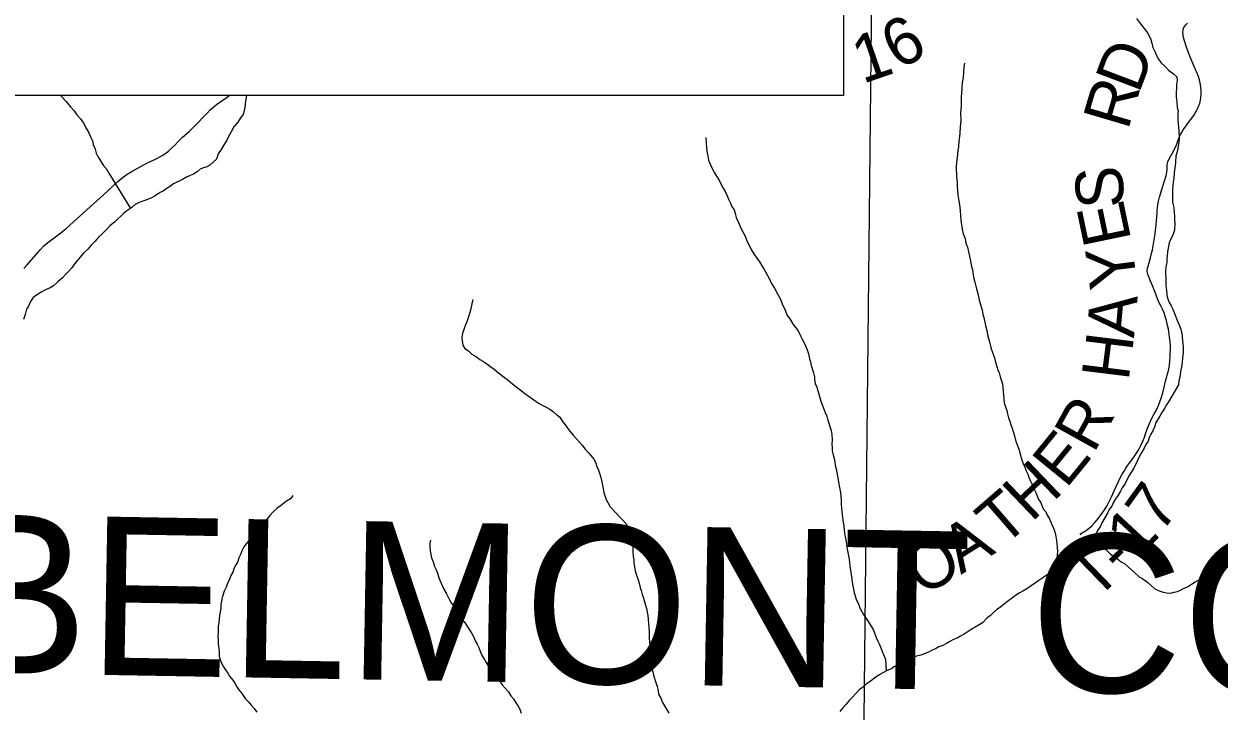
# Model space of a CAD drawing. Extents: x 0 to 34, y 0 to 22.
# Drawn here: x 27.832 to 29.261, y 14.653 to 15.474 of the extents above; entities that cross this region are included whole.
import ezdxf

# ---------------------------------------------------------------- set-up
doc = ezdxf.new("R2010")
doc.units = 0
for name, color, linetype in [('GM_X_Corporation', 7, 'Continuous'), ('GM_X_County_Text', 7, 'Continuous'), ('GM_X_Minor_River', 7, 'Continuous'), ('GM_X_Township_Road', 7, 'Continuous'), ('GM_X_Township_Road_Text', 7, 'Continuous'), ('SH_Data', 7, 'Continuous')]:
    doc.layers.add(name, color=color, linetype=linetype)

msp = doc.modelspace()

# ---------------------------------------------------------------- linework, layer by layer
at = {"layer": 'GM_X_Corporation'}
msp.add_lwpolyline([(28.8464, 15.5116), (29.8543, 15.4933), (29.8316, 14.4749), (28.8354, 14.4926)], close=True, dxfattribs=at)
at = {"layer": 'GM_X_Minor_River'}
for points in [[(29.1627, 15.4808), (29.1673, 15.4744), (29.172, 15.4688), (29.1758, 15.4636), (29.1782, 15.4594), (29.1798, 15.4557), (29.181, 15.4515), (29.1822, 15.4462), (29.1849, 15.4406), (29.1865, 15.4365), (29.1889, 15.4323), (29.1916, 15.4282), (29.1974, 15.423), (29.2008, 15.4193), (29.207, 15.4148), (29.2108, 15.4111), (29.2113, 15.4066), (29.2106, 15.402), (29.2103, 15.3978), (29.21, 15.3925), (29.2101, 15.3872), (29.211, 15.3808), (29.2114, 15.3744), (29.2123, 15.3706), (29.212, 15.3668), (29.2121, 15.3592), (29.213, 15.3505), (29.2134, 15.3467), (29.2136, 15.338), (29.2133, 15.3327), (29.2126, 15.3281), (29.2116, 15.3232), (29.2098, 15.3163), (29.2092, 15.3091), (29.2089, 15.3042), (29.2082, 15.3), (29.2075, 15.2954), (29.2072, 15.2905), (29.2066, 15.2852), (29.2059, 15.2772), (29.2057, 15.2715), (29.2058, 15.2613), (29.2071, 15.2549), (29.2076, 15.2484), (29.208, 15.2446), (29.2081, 15.2401), (29.2086, 15.2356), (29.2079, 15.2276), (29.2061, 15.2219), (29.2025, 15.215), (29.2014, 15.2104), (29.1997, 15.202), (29.1994, 15.1971), (29.1991, 15.1933), (29.1988, 15.1888), (29.1977, 15.1838), (29.1974, 15.1789), (29.1977, 15.1664), (29.1977, 15.1611), (29.1986, 15.1562), (29.1991, 15.1497), (29.2003, 15.1456), (29.2019, 15.1411), (29.2042, 15.1373), (29.2062, 15.1332), (29.2085, 15.1271), (29.2109, 15.1207), (29.2133, 15.1155), (29.2157, 15.1095), (29.2165, 15.1057), (29.2173, 15.1015), (29.2178, 15.0947), (29.2183, 15.089), (29.2184, 15.0849), (29.2184, 15.0811), (29.2178, 15.075), (29.2171, 15.0693), (29.2165, 15.064), (29.2154, 15.0587), (29.2144, 15.0518), (29.2133, 15.0476), (29.2127, 15.0427)], [(28.957, 15.4274), (28.9563, 15.4236), (28.9557, 15.4164), (28.9554, 15.4103), (28.9544, 15.4043), (28.9535, 15.3917), (28.9532, 15.3872), (28.9529, 15.3807), (28.953, 15.3762), (28.9524, 15.3675), (28.9525, 15.3591), (28.9519, 15.3512), (28.9513, 15.3439), (28.951, 15.3394), (28.9503, 15.3344), (28.9497, 15.3272), (28.949, 15.3234), (28.9484, 15.3143), (28.9473, 15.309), (28.9471, 15.3029), (28.9473, 15.2919), (28.9481, 15.2851), (28.9482, 15.2791), (28.9487, 15.2753), (28.9491, 15.27), (28.9504, 15.2628), (28.9513, 15.2552), (28.9518, 15.2507), (28.9527, 15.2397), (28.9544, 15.2291), (28.9556, 15.2235), (28.9576, 15.2178), (28.9585, 15.2121), (28.9604, 15.2076), (28.9617, 15.202), (28.9629, 15.1967), (28.9641, 15.191), (28.965, 15.1857), (28.9666, 15.1801), (28.9679, 15.1714), (28.9695, 15.1657), (28.9715, 15.1574), (28.9732, 15.1502), (28.9744, 15.1442), (28.976, 15.1389), (28.978, 15.1321), (28.9789, 15.1268), (28.9801, 15.1231), (28.9821, 15.1136), (28.9837, 15.1076), (28.9846, 15.1027), (28.9858, 15.0982), (28.987, 15.094), (28.989, 15.0857), (28.9914, 15.0793), (28.993, 15.0752), (28.9942, 15.0699), (28.9958, 15.0646), (28.9967, 15.0608), (28.9986, 15.0571), (28.9998, 15.0525), (29.0011, 15.0476), (29.0023, 15.0439)], [(27.8765, 15.3888), (27.8774, 15.3875), (27.8828, 15.3816), (27.8882, 15.3752), (27.8925, 15.3704), (27.8956, 15.3655), (27.9002, 15.361), (27.9037, 15.3558), (27.9072, 15.349), (27.9099, 15.3441), (27.9123, 15.3385), (27.9143, 15.3347), (27.9151, 15.3302), (27.9175, 15.3246), (27.9187, 15.32), (27.9206, 15.3159), (27.9238, 15.3106), (27.9273, 15.3054), (27.9307, 15.3013)], [(28.0983, 15.3888), (28.0977, 15.3846), (28.097, 15.3789), (28.0967, 15.3743), (28.0946, 15.366), (28.0913, 15.3621), (28.0883, 15.3568), (28.0835, 15.3514)], [(28.0835, 15.3514), (28.0802, 15.3452), (28.0769, 15.3399), (28.0751, 15.3353), (28.0721, 15.3311), (28.0681, 15.3242), (28.0648, 15.3192), (28.0626, 15.3127), (28.0548, 15.3054), (28.051, 15.3034), (28.0469, 15.3022), (28.0431, 15.3006), (28.0394, 15.2975), (28.0353, 15.2948), (28.0311, 15.2932), (28.0266, 15.2912), (28.0218, 15.2885), (28.0113, 15.283), (28.0075, 15.2803), (28.0038, 15.2779), (27.9989, 15.2744), (27.9952, 15.2729), (27.9892, 15.269), (27.9851, 15.2666), (27.9783, 15.2635), (27.9734, 15.2619), (27.9693, 15.2603), (27.9652, 15.2583), (27.9614, 15.2548), (27.9554, 15.2509), (27.9513, 15.2478), (27.9405, 15.2374), (27.9349, 15.2328), (27.9312, 15.2285), (27.9257, 15.2231), (27.9216, 15.2193), (27.9175, 15.2146), (27.9126, 15.2096), (27.9089, 15.205), (27.9037, 15.2004), (27.893, 15.1873), (27.8897, 15.1827), (27.8859, 15.1788), (27.8822, 15.1746), (27.8785, 15.1707), (27.8729, 15.1661), (27.8677, 15.1611), (27.8636, 15.1587), (27.8583, 15.1564), (27.8538, 15.154), (27.8486, 15.1509), (27.8433, 15.1474), (27.8404, 15.1424), (27.8378, 15.137), (27.8356, 15.1332), (27.8339, 15.1267), (27.8317, 15.121)], [(28.6479, 15.3386), (28.648, 15.3321), (28.6485, 15.3268), (28.6489, 15.3223), (28.6502, 15.3162), (28.651, 15.3113), (28.6534, 15.3057), (28.6557, 15.3008), (28.6581, 15.2963), (28.6604, 15.2925), (28.6631, 15.2884), (28.6663, 15.2816), (28.6686, 15.2779), (28.671, 15.2738), (28.6733, 15.2689), (28.6749, 15.2647), (28.6773, 15.2599), (28.6788, 15.2561), (28.6816, 15.252), (28.6828, 15.2478), (28.684, 15.2429), (28.6867, 15.2369), (28.6899, 15.2294), (28.693, 15.2237), (28.6954, 15.2185), (28.6973, 15.2143), (28.6993, 15.2106), (28.7024, 15.2038), (28.7052, 15.1993), (28.7087, 15.1941), (28.7118, 15.19), (28.7141, 15.1858), (28.7168, 15.1821), (28.7239, 15.1693), (28.7262, 15.1641), (28.7297, 15.1584), (28.7336, 15.1517), (28.7368, 15.1453), (28.7395, 15.1385), (28.7423, 15.1333), (28.745, 15.1257), (28.7481, 15.1216), (28.752, 15.1149), (28.7555, 15.1111), (28.7582, 15.1074), (28.761, 15.1014), (28.7629, 15.0972), (28.7653, 15.0931), (28.7669, 15.0893), (28.7688, 15.0848), (28.7704, 15.0799), (28.7717, 15.0739), (28.7729, 15.0701), (28.7737, 15.066), (28.7765, 15.0573), (28.7777, 15.0524), (28.7778, 15.0486), (28.7786, 15.0444), (28.7806, 15.0399)], [(27.9307, 15.3013), (27.9339, 15.296), (27.9596, 15.2536)], [(28.369, 15.1449), (28.3679, 15.1395), (28.3669, 15.1335), (28.3655, 15.1293), (28.3644, 15.1251), (28.3619, 15.1182), (28.3604, 15.1144), (28.3582, 15.109), (28.3568, 15.1045), (28.3561, 15.0995), (28.3562, 15.0954), (28.3571, 15.0901), (28.3594, 15.0863), (28.364, 15.0834), (28.3678, 15.0796), (28.3736, 15.0763), (28.3774, 15.073), (28.3812, 15.0712), (28.3858, 15.0678), (28.3908, 15.0641), (28.3946, 15.0615), (28.4, 15.0571), (28.4065, 15.0519), (28.4119, 15.0478), (28.4211, 15.0404), (28.4253, 15.0371), (28.4299, 15.0337)], [(28.7806, 15.0399), (28.7854, 15.0231), (28.7905, 15.0095), (28.7924, 15.0053), (28.7936, 15.0004), (28.7975, 14.9883), (28.7983, 14.9833), (28.7987, 14.9769), (28.7984, 14.9719), (28.7988, 14.9678), (28.7988, 14.964), (28.8, 14.959), (28.8012, 14.9545), (28.8019, 14.9507), (28.8024, 14.9465), (28.8035, 14.9424), (28.8043, 14.9378), (28.8051, 14.9336), (28.8059, 14.9291), (28.8067, 14.9241), (28.8087, 14.9139), (28.8091, 14.9097), (28.8095, 14.9044), (28.8096, 14.9002), (28.81, 14.8953), (28.8104, 14.8911), (28.8112, 14.8839), (28.812, 14.8786), (28.8128, 14.8737), (28.8132, 14.8695), (28.8136, 14.8657), (28.8144, 14.8611), (28.8152, 14.8573), (28.816, 14.8524), (28.8168, 14.846), (28.8184, 14.8384), (28.8192, 14.8342), (28.8196, 14.83), (28.8204, 14.8236), (28.8212, 14.8183), (28.8221, 14.8107), (28.8225, 14.8069), (28.8236, 14.8023), (28.8244, 14.7985), (28.8252, 14.794), (28.828, 14.7853), (28.8299, 14.7815), (28.8318, 14.7762), (28.8341, 14.7716), (28.8364, 14.7679), (28.8395, 14.7633), (28.8426, 14.7584), (28.848, 14.7494), (28.8499, 14.7448), (28.8514, 14.7407), (28.853, 14.7369), (28.8553, 14.7323), (28.8568, 14.7282), (28.8588, 14.7232), (28.8611, 14.7183), (28.8626, 14.7142), (28.8634, 14.7003)], [(29.2127, 15.0427), (29.2008, 15.0224), (29.1982, 15.0186), (29.196, 15.0144), (29.193, 15.0098), (29.1904, 15.0052), (29.1859, 14.9976), (29.1844, 14.9934), (29.1826, 14.9884), (29.1796, 14.9838), (29.1777, 14.9796), (29.1766, 14.9754), (29.174, 14.9712), (29.1718, 14.967), (29.1692, 14.9621), (29.1658, 14.9567), (29.1639, 14.9521), (29.1595, 14.943), (29.1565, 14.9388), (29.1539, 14.9342), (29.1516, 14.93), (29.149, 14.9246), (29.1457, 14.9197), (29.1434, 14.9155), (29.1408, 14.9109), (29.1374, 14.9063), (29.1348, 14.9017), (29.1333, 14.8975), (29.13, 14.8937), (29.1281, 14.8891), (29.1214, 14.8776), (29.1192, 14.8731), (29.1162, 14.8685), (29.1139, 14.8643), (29.1113, 14.8605), (29.1076, 14.8566), (29.1016, 14.849), (29.0971, 14.8447), (29.0933, 14.842), (29.0895, 14.839), (29.0854, 14.8351), (29.0756, 14.8278), (29.0711, 14.8251), (29.0673, 14.8224), (29.0632, 14.8201), (29.0591, 14.8174), (29.0545, 14.8147), (29.0508, 14.812), (29.0459, 14.8089), (29.0417, 14.8059), (29.0316, 14.7989), (29.0267, 14.7958), (29.0225, 14.7935), (29.018, 14.7908), (29.0142, 14.7881), (29.0101, 14.7847), (29.0048, 14.7808), (28.9999, 14.777), (28.9958, 14.7739), (28.9917, 14.7704), (28.9879, 14.767), (28.9838, 14.7635), (28.9785, 14.7582), (28.9744, 14.7555), (28.9699, 14.7528), (28.9661, 14.7508), (28.9612, 14.7477), (28.9567, 14.7447), (28.9521, 14.7423), (28.9484, 14.7396), (28.9439, 14.7381), (28.9393, 14.7358), (28.9356, 14.7334), (28.931, 14.7311), (28.9265, 14.7292), (28.9224, 14.7269), (28.9182, 14.7253), (28.9141, 14.723), (28.9046, 14.7195), (28.9008, 14.7187), (28.8967, 14.7171), (28.8914, 14.7148), (28.8873, 14.7132), (28.882, 14.7105), (28.8775, 14.7078), (28.8733, 14.7059), (28.8696, 14.7032), (28.8647, 14.7009), (28.8548, 14.6958), (28.8511, 14.6932), (28.8443, 14.6881), (28.8394, 14.6847), (28.8349, 14.6808), (28.8311, 14.6778), (28.8229, 14.6693), (28.8191, 14.6651), (28.8154, 14.6609), (28.8116, 14.6563), (28.8079, 14.6521)], [(29.0023, 15.0439), (29.0043, 15.0213), (29.0062, 15.0164), (29.0078, 15.0119), (29.0086, 15.0081), (29.0098, 15.0031), (29.0113, 14.9994), (29.0125, 14.9948), (29.014, 14.991), (29.0152, 14.9869), (29.0168, 14.9819), (29.0175, 14.9781), (29.0187, 14.9743), (29.0207, 14.969), (29.0222, 14.9645), (29.0238, 14.9588), (29.0253, 14.9543), (29.0273, 14.9482), (29.0292, 14.9444), (29.0307, 14.9399), (29.0327, 14.9361), (29.0338, 14.9323), (29.0358, 14.9274), (29.0385, 14.9229), (29.04, 14.9187), (29.0423, 14.9141), (29.0454, 14.9058), (29.0481, 14.902), (29.0493, 14.8983), (29.0512, 14.8945), (29.0543, 14.8907), (29.0558, 14.8869), (29.0581, 14.8831), (29.0604, 14.8786), (29.0643, 14.8695), (29.0655, 14.8653), (29.0663, 14.8612), (29.067, 14.8566), (29.0675, 14.8521), (29.0679, 14.8483), (29.0683, 14.8437), (29.068, 14.8392), (29.0657, 14.8215)], [(28.4299, 15.0337), (28.4477, 15.0208), (28.453, 15.0182), (28.4568, 15.016), (28.461, 15.0137), (28.4656, 15.0103), (28.4694, 15.0069), (28.4732, 15.0039), (28.4755, 15.0002), (28.4785, 14.9964), (28.4816, 14.9922), (28.4851, 14.9873), (28.4889, 14.9824), (28.4962, 14.9745), (28.5, 14.9707), (28.503, 14.9662), (28.508, 14.9609), (28.5141, 14.9534), (28.5161, 14.9489), (28.5172, 14.9451), (28.5195, 14.9405), (28.5211, 14.936), (28.5223, 14.9318), (28.5234, 14.9269), (28.5242, 14.9227), (28.525, 14.9189), (28.5258, 14.914), (28.527, 14.9102), (28.5285, 14.9057), (28.5305, 14.9019), (28.5335, 14.897), (28.5408, 14.889), (28.5439, 14.8853), (28.5481, 14.8811), (28.5519, 14.877), (28.5542, 14.8732), (28.5561, 14.869), (28.5577, 14.8653), (28.5592, 14.8603), (28.5604, 14.8558), (28.5605, 14.8474), (28.5605, 14.8429), (28.5609, 14.8376), (28.5617, 14.8338), (28.5618, 14.83), (28.5634, 14.8201), (28.5649, 14.8152), (28.5668, 14.8095), (28.568, 14.8057), (28.5692, 14.8004), (28.5704, 14.7966), (28.5715, 14.7921), (28.5731, 14.7875), (28.5754, 14.7792), (28.5766, 14.7754), (28.5774, 14.7708), (28.5782, 14.7667), (28.5786, 14.7625), (28.5794, 14.7526), (28.5799, 14.7469), (28.5799, 14.7393), (28.5808, 14.7317), (28.5808, 14.7237), (28.5812, 14.7192), (28.5817, 14.7124), (28.5825, 14.7078), (28.5833, 14.7032), (28.5844, 14.6995), (28.5852, 14.6953), (28.588, 14.6866), (28.5895, 14.682), (28.5907, 14.6771), (28.5911, 14.6729), (28.5938, 14.668), (28.5961, 14.6627), (28.5984, 14.6589), (28.6007, 14.6548), (28.6034, 14.6502)], [(28.154, 14.9102), (28.151, 14.9064), (28.1465, 14.9037), (28.1427, 14.901), (28.139, 14.898), (28.1352, 14.8953), (28.1307, 14.8914), (28.1262, 14.8864), (28.1232, 14.8826), (28.1198, 14.8788), (28.1161, 14.8742), (28.1119, 14.8696), (28.1089, 14.8654), (28.1048, 14.8612), (28.1018, 14.857), (28.0984, 14.8531), (28.0954, 14.8489), (28.0928, 14.8443), (28.0917, 14.8405), (28.0895, 14.836), (28.088, 14.8314), (28.0858, 14.8276), (28.0839, 14.8237), (28.0821, 14.8188), (28.0798, 14.8146), (28.078, 14.81), (28.0757, 14.8054), (28.0743, 14.8009), (28.0717, 14.7959), (28.0706, 14.7921), (28.0695, 14.7883), (28.0687, 14.7841), (28.068, 14.7803), (28.0677, 14.7757), (28.0669, 14.7712), (28.0662, 14.767), (28.0655, 14.7582), (28.0648, 14.754), (28.0645, 14.7502), (28.0645, 14.7457), (28.0642, 14.7419), (28.0646, 14.7373), (28.0646, 14.7324), (28.0654, 14.7274), (28.0658, 14.7229), (28.0659, 14.7183), (28.0671, 14.7138), (28.0686, 14.71), (28.0709, 14.7055), (28.0732, 14.7017), (28.0763, 14.6979), (28.0782, 14.6941), (28.082, 14.6896), (28.0847, 14.6858), (28.087, 14.6817), (28.0893, 14.6779), (28.0932, 14.673), (28.0966, 14.6681), (28.1008, 14.6636), (28.1042, 14.6598), (28.1077, 14.6556), (28.1108, 14.6511)], [(28.3184, 14.857), (28.3177, 14.8528), (28.3177, 14.8487), (28.3181, 14.8441), (28.3197, 14.8358), (28.3217, 14.8312), (28.3232, 14.8255), (28.3252, 14.8214), (28.3271, 14.8164), (28.3283, 14.8119), (28.3325, 14.8028), (28.3344, 14.7983), (28.3371, 14.7937), (28.341, 14.7862), (28.3433, 14.782), (28.3467, 14.7775), (28.3487, 14.7737), (28.3513, 14.7695), (28.3536, 14.7658), (28.3563, 14.762), (28.3598, 14.7578), (28.3678, 14.7454), (28.3705, 14.7408), (28.3721, 14.7367), (28.3744, 14.7325), (28.3763, 14.7284), (28.3782, 14.7231), (28.3802, 14.7185), (28.3829, 14.7144), (28.3852, 14.7106), (28.3879, 14.706), (28.3909, 14.7011), (28.3944, 14.6966), (28.3974, 14.6921), (28.402, 14.6875), (28.4043, 14.6838), (28.4078, 14.68), (28.4116, 14.6755), (28.4147, 14.6709), (28.4177, 14.6672), (28.4204, 14.6623), (28.4235, 14.6585), (28.4254, 14.6547), (28.427, 14.6502)], [(29.1113, 14.8604), (29.1316, 14.8401), (29.1358, 14.8375), (29.1403, 14.8341), (29.1445, 14.8311), (29.1487, 14.8285), (29.1605, 14.818), (29.1659, 14.8131), (29.1704, 14.8108), (29.1762, 14.8063), (29.18, 14.8026), (29.1845, 14.7988), (29.1899, 14.7962), (29.1944, 14.7947), (29.199, 14.794), (29.2035, 14.7937), (29.2077, 14.7949), (29.2115, 14.7957), (29.2152, 14.7972), (29.219, 14.7991), (29.2235, 14.8011), (29.2284, 14.8042), (29.2329, 14.8072), (29.2405, 14.8111), (29.2446, 14.8134), (29.2495, 14.8158), (29.2533, 14.8177), (29.2575, 14.8196), (29.262, 14.8208)]]:
    msp.add_lwpolyline(points, dxfattribs=at)
at = {"layer": 'GM_X_Township_Road'}
for points in [[(29.2361, 15.3737), (29.2373, 15.3768), (29.2382, 15.3794), (29.239, 15.3832), (29.2395, 15.3864), (29.2398, 15.3898), (29.2399, 15.3936), (29.2397, 15.3988), (29.2389, 15.4039), (29.2381, 15.4075), (29.2367, 15.4115), (29.2315, 15.4234), (29.2291, 15.4291), (29.2263, 15.4359), (29.2247, 15.4402), (29.2229, 15.4454), (29.2197, 15.4554), (29.2186, 15.4596), (29.2183, 15.4617), (29.2182, 15.4645), (29.2184, 15.4669), (29.2186, 15.4682), (29.2194, 15.4701), (29.2203, 15.4718), (29.2215, 15.4734), (29.2235, 15.4753)], [(27.8323, 15.1818), (27.8362, 15.1864), (27.8469, 15.1987), (27.8519, 15.2044), (27.8563, 15.2089), (27.8608, 15.2128), (27.8686, 15.2185), (27.8751, 15.2233), (27.8829, 15.2298), (27.8918, 15.2377), (27.9076, 15.2522), (27.9274, 15.2701), (27.9445, 15.2861), (27.9493, 15.2901), (27.9557, 15.2947), (27.9624, 15.2989), (27.9795, 15.3078), (27.9904, 15.3132), (27.995, 15.3155), (27.9983, 15.3174), (28.0025, 15.3202), (28.0052, 15.3224), (28.0086, 15.3253), (28.0127, 15.3294), (28.017, 15.334), (28.0218, 15.3388), (28.0299, 15.3459), (28.0361, 15.3518), (28.0514, 15.3677), (28.0552, 15.3715), (28.0627, 15.3779), (28.0695, 15.3829), (28.0749, 15.3865), (28.0777, 15.3888)], [(29.0955, 14.8633), (29.0962, 14.8645), (29.0982, 14.8661), (29.1003, 14.8675), (29.1029, 14.8691), (29.1065, 14.8718), (29.1097, 14.8744), (29.1129, 14.878), (29.1156, 14.8813), (29.1186, 14.885), (29.1217, 14.8892), (29.1239, 14.8926), (29.1271, 14.8978), (29.1301, 14.9032), (29.1328, 14.9086), (29.136, 14.9161), (29.1436, 14.9322), (29.1456, 14.9359), (29.1478, 14.9395), (29.15, 14.9431), (29.1523, 14.9466), (29.1548, 14.95), (29.1573, 14.9534), (29.1596, 14.9564), (29.1626, 14.9609), (29.1653, 14.9656), (29.1678, 14.9703), (29.1701, 14.9752), (29.1721, 14.9802), (29.1738, 14.9853), (29.1758, 14.991), (29.1781, 14.9965), (29.1807, 15.002), (29.1834, 15.0073), (29.186, 15.0121), (29.1885, 15.0172), (29.1907, 15.0223), (29.1923, 15.0268), (29.1941, 15.0333), (29.1957, 15.0399), (29.1975, 15.0472), (29.201, 15.06), (29.202, 15.0658), (29.2027, 15.0711), (29.2031, 15.0765), (29.2032, 15.089), (29.2028, 15.0951), (29.2023, 15.0992), (29.2018, 15.1033), (29.2008, 15.1093), (29.1995, 15.1153), (29.1985, 15.1196), (29.1971, 15.1243), (29.1956, 15.1289), (29.1937, 15.1334), (29.1916, 15.1374), (29.1895, 15.1415), (29.1877, 15.1458), (29.186, 15.1501), (29.1845, 15.1542), (29.182, 15.1605), (29.1795, 15.1668), (29.177, 15.1732), (29.1763, 15.1749), (29.1758, 15.1768), (29.1756, 15.1782), (29.1755, 15.18), (29.1758, 15.1822), (29.1765, 15.1848), (29.1794, 15.1946), (29.1807, 15.1999), (29.1817, 15.2041), (29.1848, 15.2232), (29.1861, 15.2347), (29.1872, 15.2478), (29.1874, 15.2515), (29.1877, 15.2548), (29.1881, 15.258), (29.1888, 15.2623), (29.1902, 15.2673), (29.1958, 15.2856), (29.1974, 15.2904), (29.1985, 15.2946), (29.1991, 15.2973), (29.1992, 15.2995), (29.1994, 15.3025), (29.1995, 15.3055), (29.1996, 15.3077), (29.2, 15.3095), (29.2021, 15.3137), (29.2052, 15.3194), (29.2087, 15.3263), (29.2107, 15.3307), (29.2121, 15.3346), (29.2136, 15.3384), (29.2146, 15.341), (29.2163, 15.3443), (29.2186, 15.3477), (29.2228, 15.3536), (29.2274, 15.3599), (29.2312, 15.3648), (29.2341, 15.3695), (29.2361, 15.3737)]]:
    msp.add_lwpolyline(points, dxfattribs=at)
at = {"layer": 'SH_Data'}
msp.add_lwpolyline([(27.5407, 16.0188), (28.8122, 16.0188), (28.8122, 15.3888), (27.5407, 15.3888)], close=True, dxfattribs=at)

# ---------------------------------------------------------------- texts
at = {"layer": 'GM_X_County_Text'}
msp.add_text('BELMONT COUNTY', height=0.189394, rotation=358.998, dxfattribs=at).set_placement((27.7391, 14.6991))
at = {"layer": 'GM_X_Township_Road_Text'}
for s, rotation, p in [('6', 29.5294, (28.8785, 15.4185)), ('1', 19.0479, (28.8351, 15.4025)), ('D', 69.2052, (29.1653, 15.3899)), ('R', 73.5501, (29.1524, 15.3462)), ('S', 93.3898, (29.1482, 15.2553)), ('E', 101.7932, (29.1566, 15.2159)), ('Y', 97.2737, (29.1638, 15.1615)), ('A', 84.8578, (29.1596, 15.0982)), ('H', 82.9224, (29.1532, 15.0465)), ('R', 60.9347, (29.1115, 14.9597)), ('E', 50.7731, (29.0784, 14.9177)), ('H', 43.7222, (29.0371, 14.8775)), ('T', 40.8714, (29.0027, 14.8476)), ('7', 54.0947, (29.1919, 14.8635)), ('A', 32.172, (28.9528, 14.8154)), ('1', 47.1544, (29.1633, 14.8321)), ('O', 28.3769, (28.9053, 14.7895)), ('T', 44.0742, (29.1139, 14.7837)), ('-', 44.7162, (29.1449, 14.8137))]:
    msp.add_text(s, height=0.0568, rotation=rotation, dxfattribs=at).set_placement(p)

doc.saveas('drawing.dxf')
